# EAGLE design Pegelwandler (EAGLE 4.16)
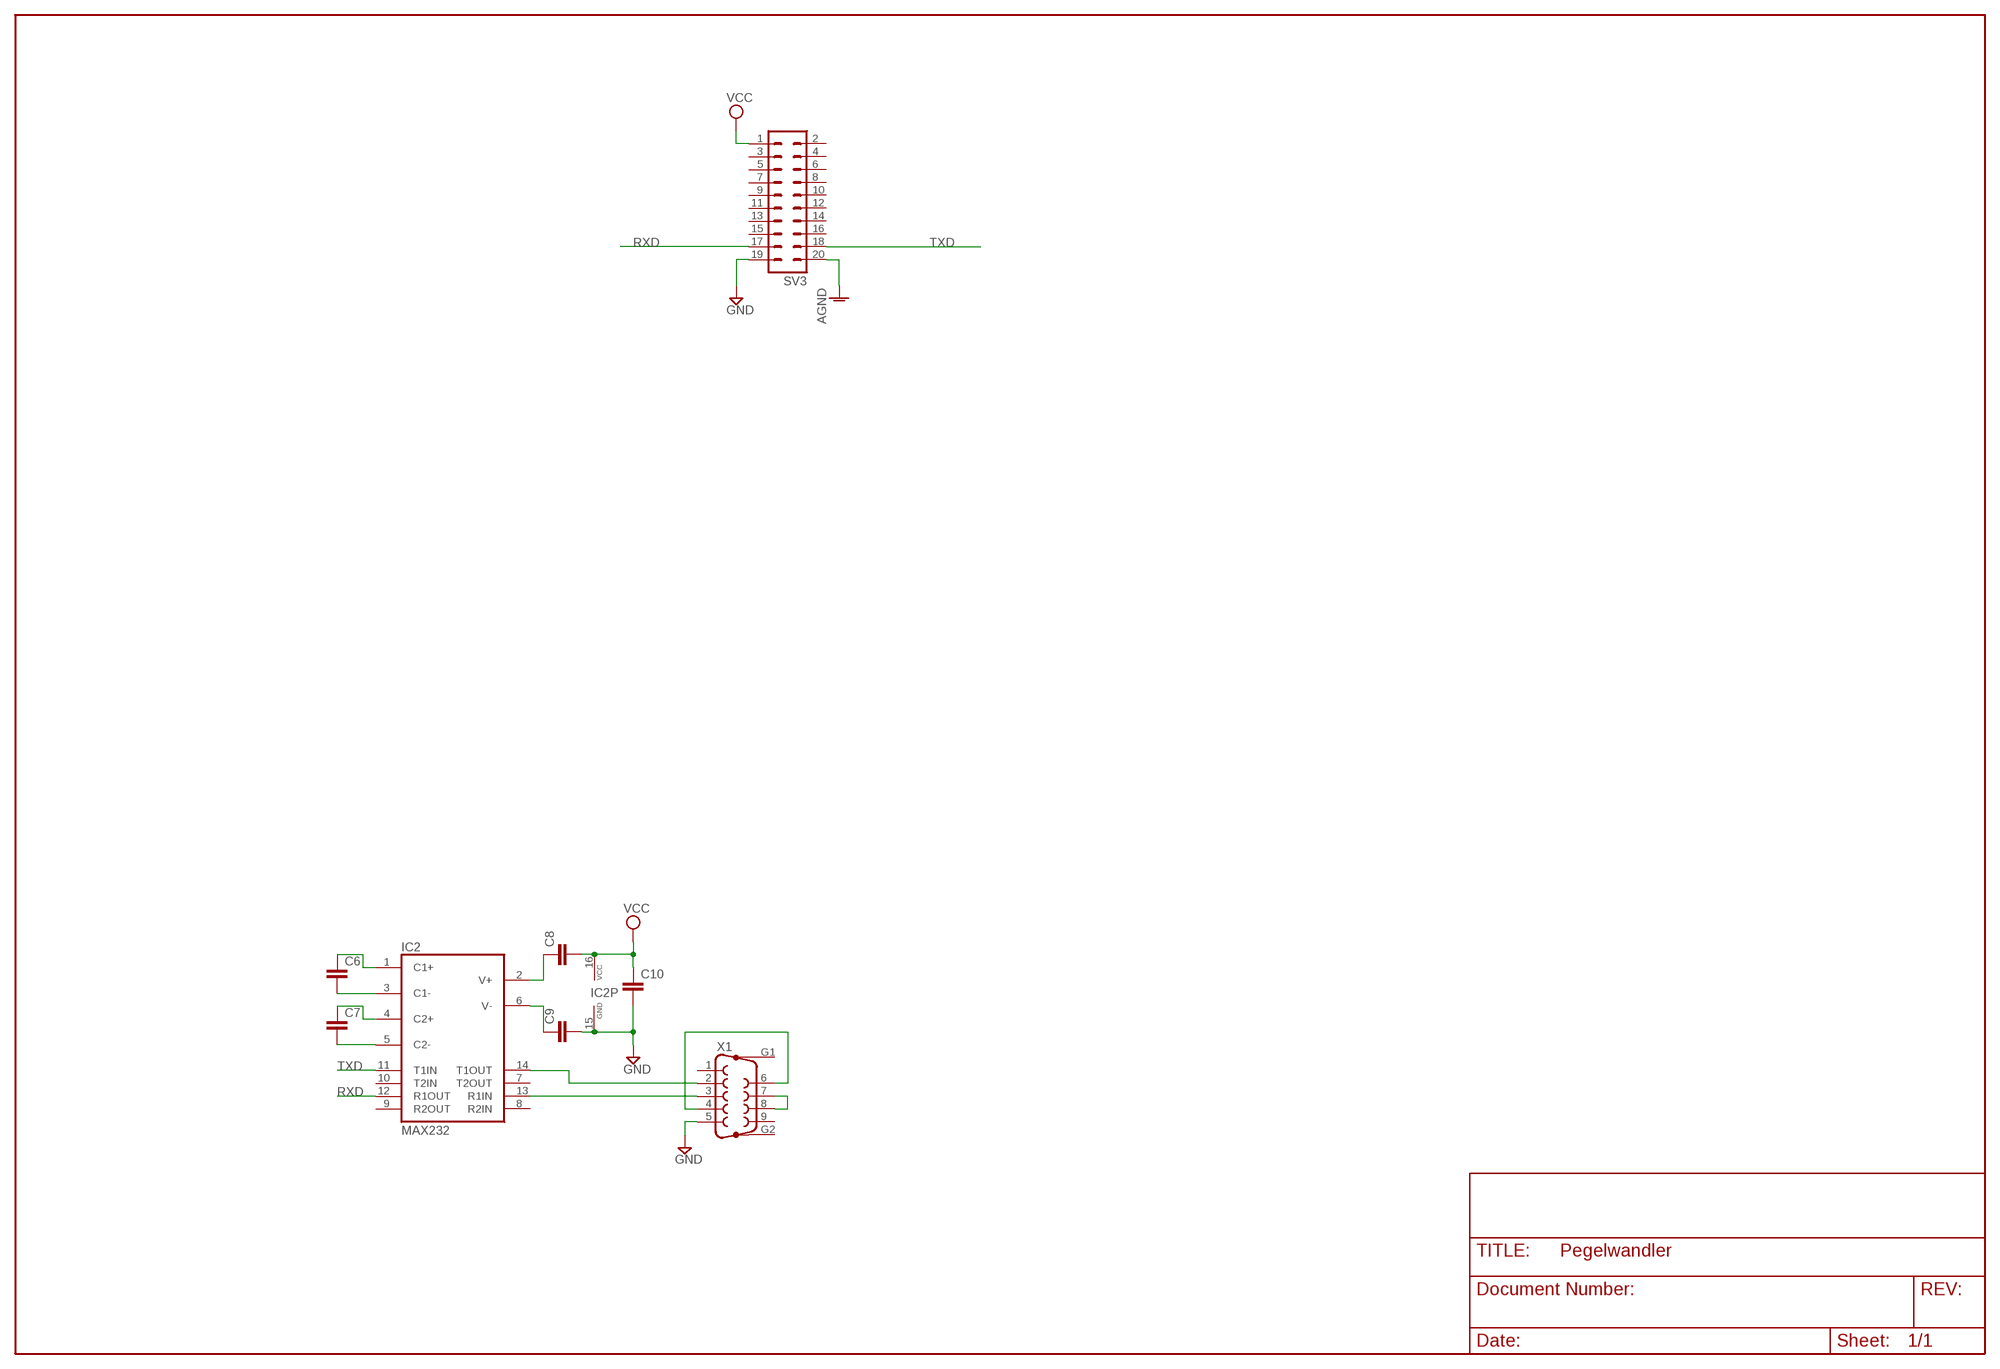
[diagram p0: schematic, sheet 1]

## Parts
C6  C-EUC1206K  [C1206K]
C7  C-EUC1206K  [C1206K]
C8  C-EUC1206K  [C1206K]
C9  C-EUC1206K  [C1206K]
C10  C-EUC1206K  [C1206K]
IC2  MAX232  [DIL16]
SV3  ML20  [ML20]
X1  F09HP  [F09HP]

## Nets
AGND: SV3.20
GND: C9.2 C10.2 IC2.15(GND) SV3.19 X1.5
N$5: IC2.13(R1IN) X1.3
N$8: X1.4 X1.6
N$9: X1.7 X1.8
N$10: IC2.14(T1OUT) X1.2
N$25: C7.2 IC2.5(C2-)
N$26: C7.1 IC2.4(C2+)
N$27: C6.2 IC2.3(C1-)
N$28: C6.1 IC2.1(C1+)
N$30: C8.1 IC2.2(V+)
N$31: C9.1 IC2.6(V-)
RXD: IC2.12(R1OUT) SV3.17
TXD: IC2.11(T1IN) SV3.18
VCC: C8.2 C10.1 IC2.16(VCC) SV3.1
Unconnected: IC2.7(T2OUT) IC2.8(R2IN) IC2.9(R2OUT) IC2.10(T2IN) SV3.2 SV3.3 SV3.4 SV3.5 SV3.6 SV3.7 SV3.8 SV3.9 SV3.10 SV3.11 SV3.12 SV3.13 SV3.14 SV3.15 SV3.16 X1.1 X1.9 X1.G1 X1.G2

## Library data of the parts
C6-C10 = rcl:C-EU: CAPACITOR, European symbol
IC2 = maxim:MAX232: RS232 TRANSEIVER
SV3 = con-harting-ml:ML20: HARTING
X1 = con-subd:F09HP: SUB-D

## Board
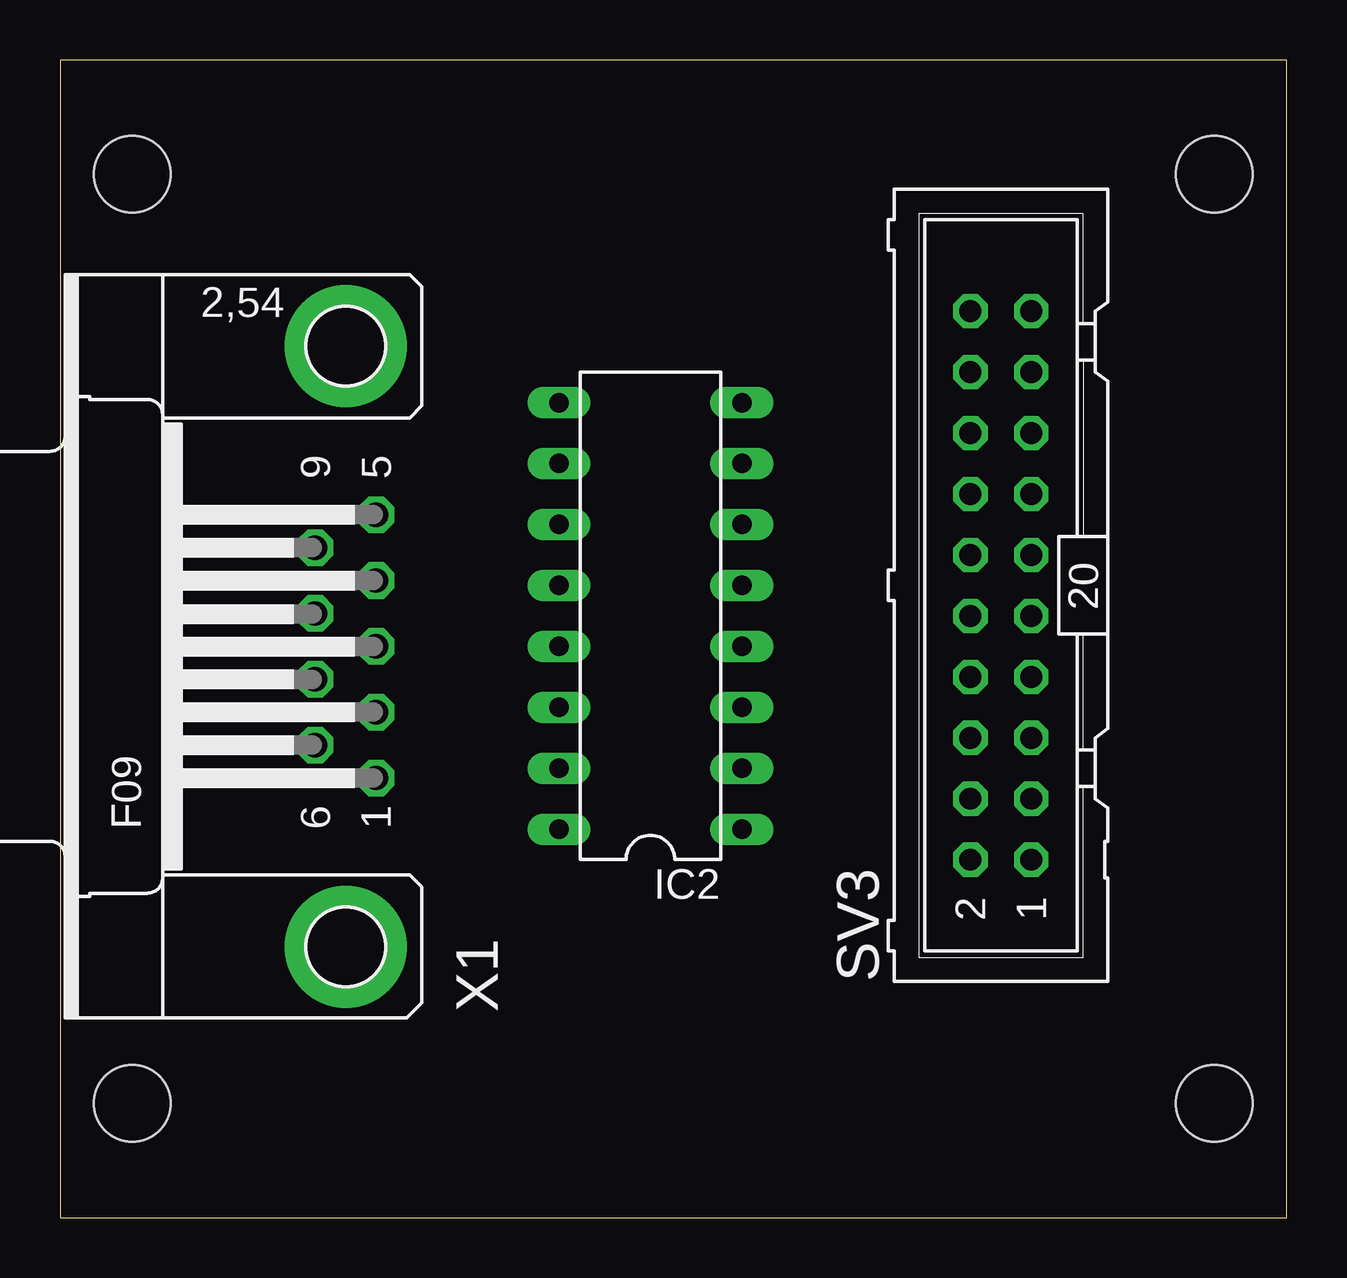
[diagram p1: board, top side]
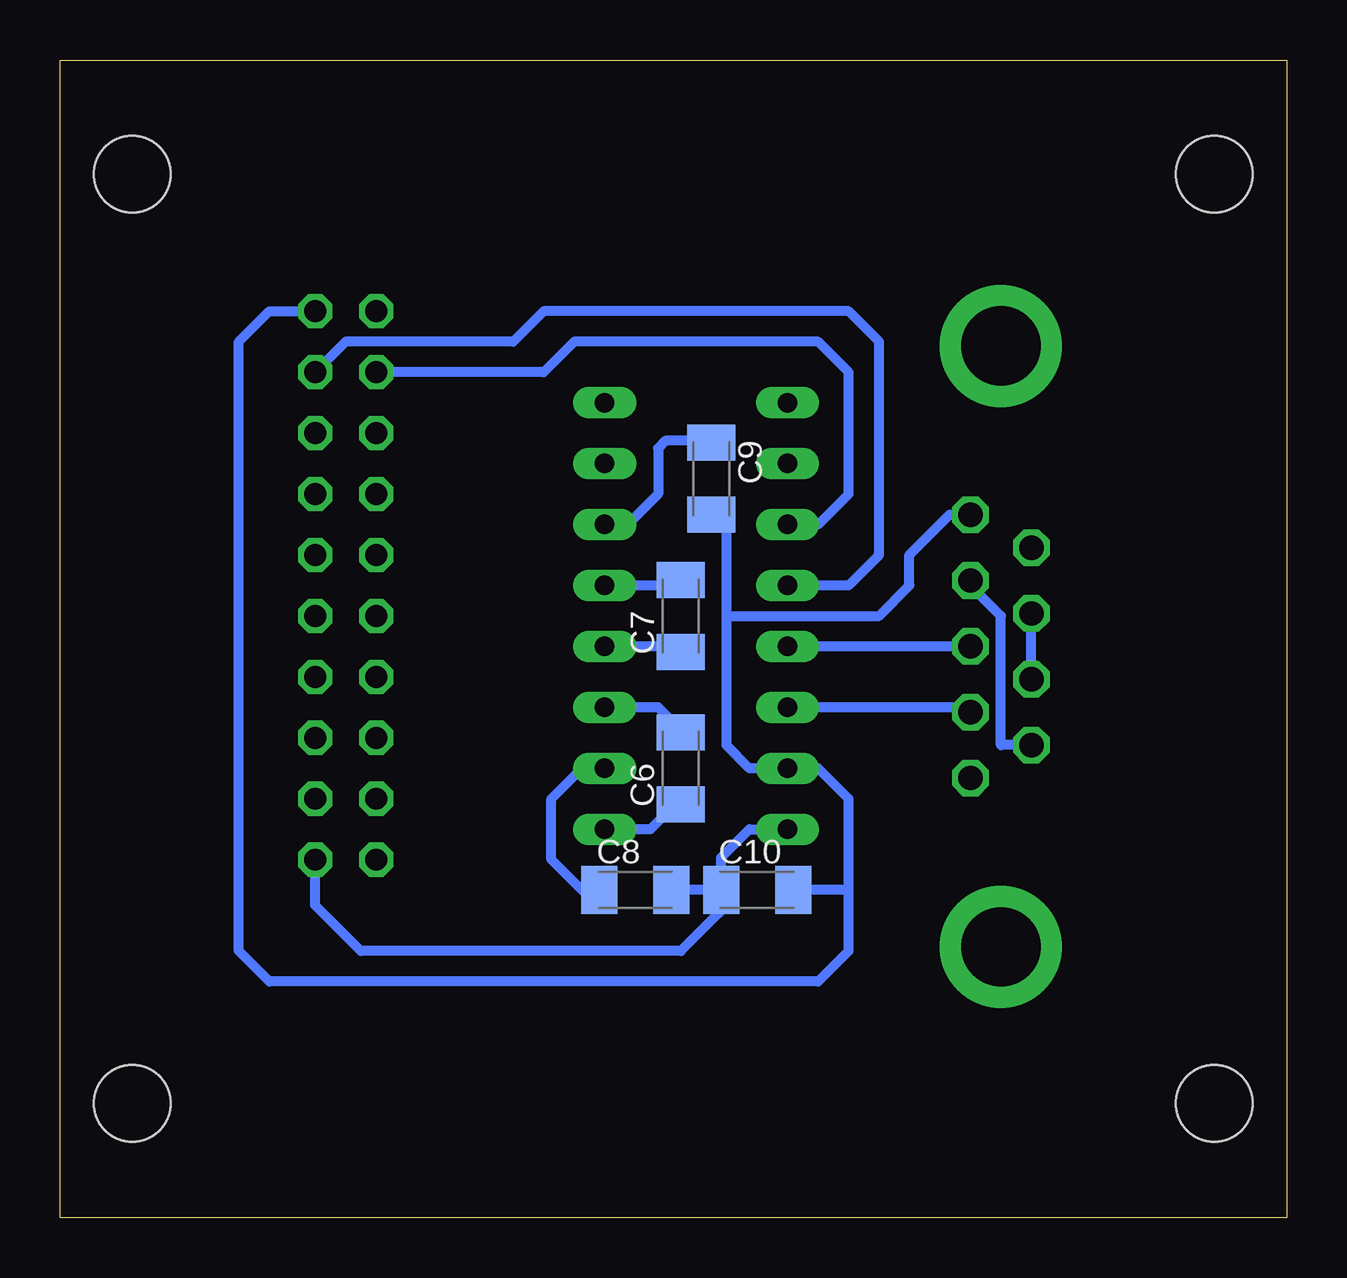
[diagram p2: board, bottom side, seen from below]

Size 51.11 x 48.25 mm. Coordinates in mm from the lower left corner, seen from the top.
Outline: 0,0 51.11,0 51.11,48.25 0,48.25 0,0
Copper layers (1*16): Top 0.035mm / dielectric 1.5mm / Bottom 0.035mm
Design rules "default": minimum track width 10mil, minimum drill 24mil, track to track 12mil, track to pad 12mil, pad to pad 12mil, via to via 12mil, smd to smd 12mil, copper to edge 40mil, drill to drill 8mil, minimum pad ring 10mil, minimum via ring 8mil, stop-mask expansion 4mil, vias tented up to drill 0mil, thermal gap 10mil
Holes 3.2 mm at 48.09,4.76 3.01,43.49 48.09,43.49 3.01,4.76

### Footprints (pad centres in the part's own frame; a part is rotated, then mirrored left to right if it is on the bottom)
C1206K = smd 1.5 x 2: 1 -1.5,0; 2 1.5,0
DIL16 = drill 0.813 long: 1 -8.89,-3.81; 2 -6.35,-3.81; 3 -3.81,-3.81; 4 -1.27,-3.81; 5 1.27,-3.81; 6 3.81,-3.81; 7 6.35,-3.81; 8 8.89,-3.81; 9 8.89,3.81; 10 6.35,3.81; 11 3.81,3.81; 12 1.27,3.81; 13 -1.27,3.81; 14 -3.81,3.81; 15 -6.35,3.81; 16 -8.89,3.81
ML20 = drill 0.914 octagon: 1 -11.43,-1.27; 2 -11.43,1.27; 3 -8.89,-1.27; 4 -8.89,1.27; 5 -6.35,-1.27; 6 -6.35,1.27; 7 -3.81,-1.27; 8 -3.81,1.27; 9 -1.27,-1.27; 10 -1.27,1.27; 11 1.27,-1.27; 12 1.27,1.27; 13 3.81,-1.27; 14 3.81,1.27; 15 6.35,-1.27; 16 6.35,1.27; 17 8.89,-1.27; 18 8.89,1.27; 19 11.43,-1.27; 20 11.43,1.27
F09HP = drill 1.016 octagon: 1 -5.486,-1.27; 2 -2.743,-1.27; 3 0,-1.27; 4 2.743,-1.27; 5 5.486,-1.27; 6 -4.115,1.27; 7 -1.372,1.27; 8 1.372,1.27; 9 4.115,1.27 | drill 3.302 pad 5.08 round: G1 -12.522,0; G2 12.522,0

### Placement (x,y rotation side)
C6  25.23,18.73 90 bottom
C7  25.23,25.08 90 bottom
C8  27.14,13.65 0 bottom
C9  23.96,30.79 270 bottom
C10  22.06,13.65 0 bottom
IC2  24.6,25.08 90 top
SV3  39.2,26.35 90 top
X1  11.9,23.81 90 top

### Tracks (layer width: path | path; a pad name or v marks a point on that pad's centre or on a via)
GND
  Bottom 0.406: 23.33,25.08 23.33,19.68 22.38,18.73 IC2.15 19.52,18.73 18.25,17.46 18.25,13.65 | 23.33,25.08 23.33,28.57 23.96,29.21 C9.2 | X1.5 14.03,29.29 15.71,27.62 15.71,26.35 16.98,25.08 23.33,25.08 | SV3.19 42.38,37.78 43.65,36.51 43.65,11.11 42.38,9.84 19.52,9.84 18.25,11.11 18.25,13.65 | 18.25,13.65 C10.2
N$5
  Bottom 0.406: X1.3 IC2.13
N$8
  Bottom 0.406: X1.6 11.9,19.69 11.9,25.08 13.17,26.35 X1.4
N$9
  Bottom 0.406: X1.7 X1.8
N$10
  Bottom 0.406: X1.2 13.17,21.27 IC2.14
N$25
  Bottom 0.406: C7.2 25.23,26.66 25.55,26.35 IC2.5
N$26
  Bottom 0.406: C7.1 25.23,23.49 25.55,23.81 IC2.4
N$27
  Bottom 0.406: C6.2 25.23,20.31 26.19,21.27 IC2.3
N$28
  Bottom 0.406: C6.1 25.46,17.23 26.5,16.19 IC2.1
N$30
  Bottom 0.406: IC2.2 29.36,18.73 30.63,17.46 30.63,14.92 29.36,13.65 C8.1 28.41,13.65
N$31
  Bottom 0.406: IC2.6 27.46,28.89 26.19,30.16 26.19,32.06 25.87,32.38 24.28,32.38 24.2,32.29 C9.1
RXD
  Bottom 0.406: IC2.12 18.25,26.35 16.98,27.62 16.98,36.51 18.25,37.78 30.95,37.78 32.22,36.51 39.2,36.51 SV3.17
TXD
  Bottom 0.406: SV3.18 30.95,35.24 29.68,36.51 19.52,36.51 18.25,35.24 18.25,30.16 19.52,28.89 IC2.11
VCC
  Bottom 0.406: 25.87,13.65 C8.2 23.65,13.65 | IC2.16 22.38,16.19 23.56,15 C10.1 23.65,13.65 | SV3.1 40.48,13.01 38.57,11.11 25.23,11.11 23.65,12.69 23.65,13.65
